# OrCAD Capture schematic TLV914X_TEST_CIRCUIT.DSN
size A; title: TLV914x 18V, Rail-to-Rail I/O, 110kHz Low Power; rev: 1.0; note: Datasheet: SBOSAM4 - DEC 2024 REV. FEB 2026
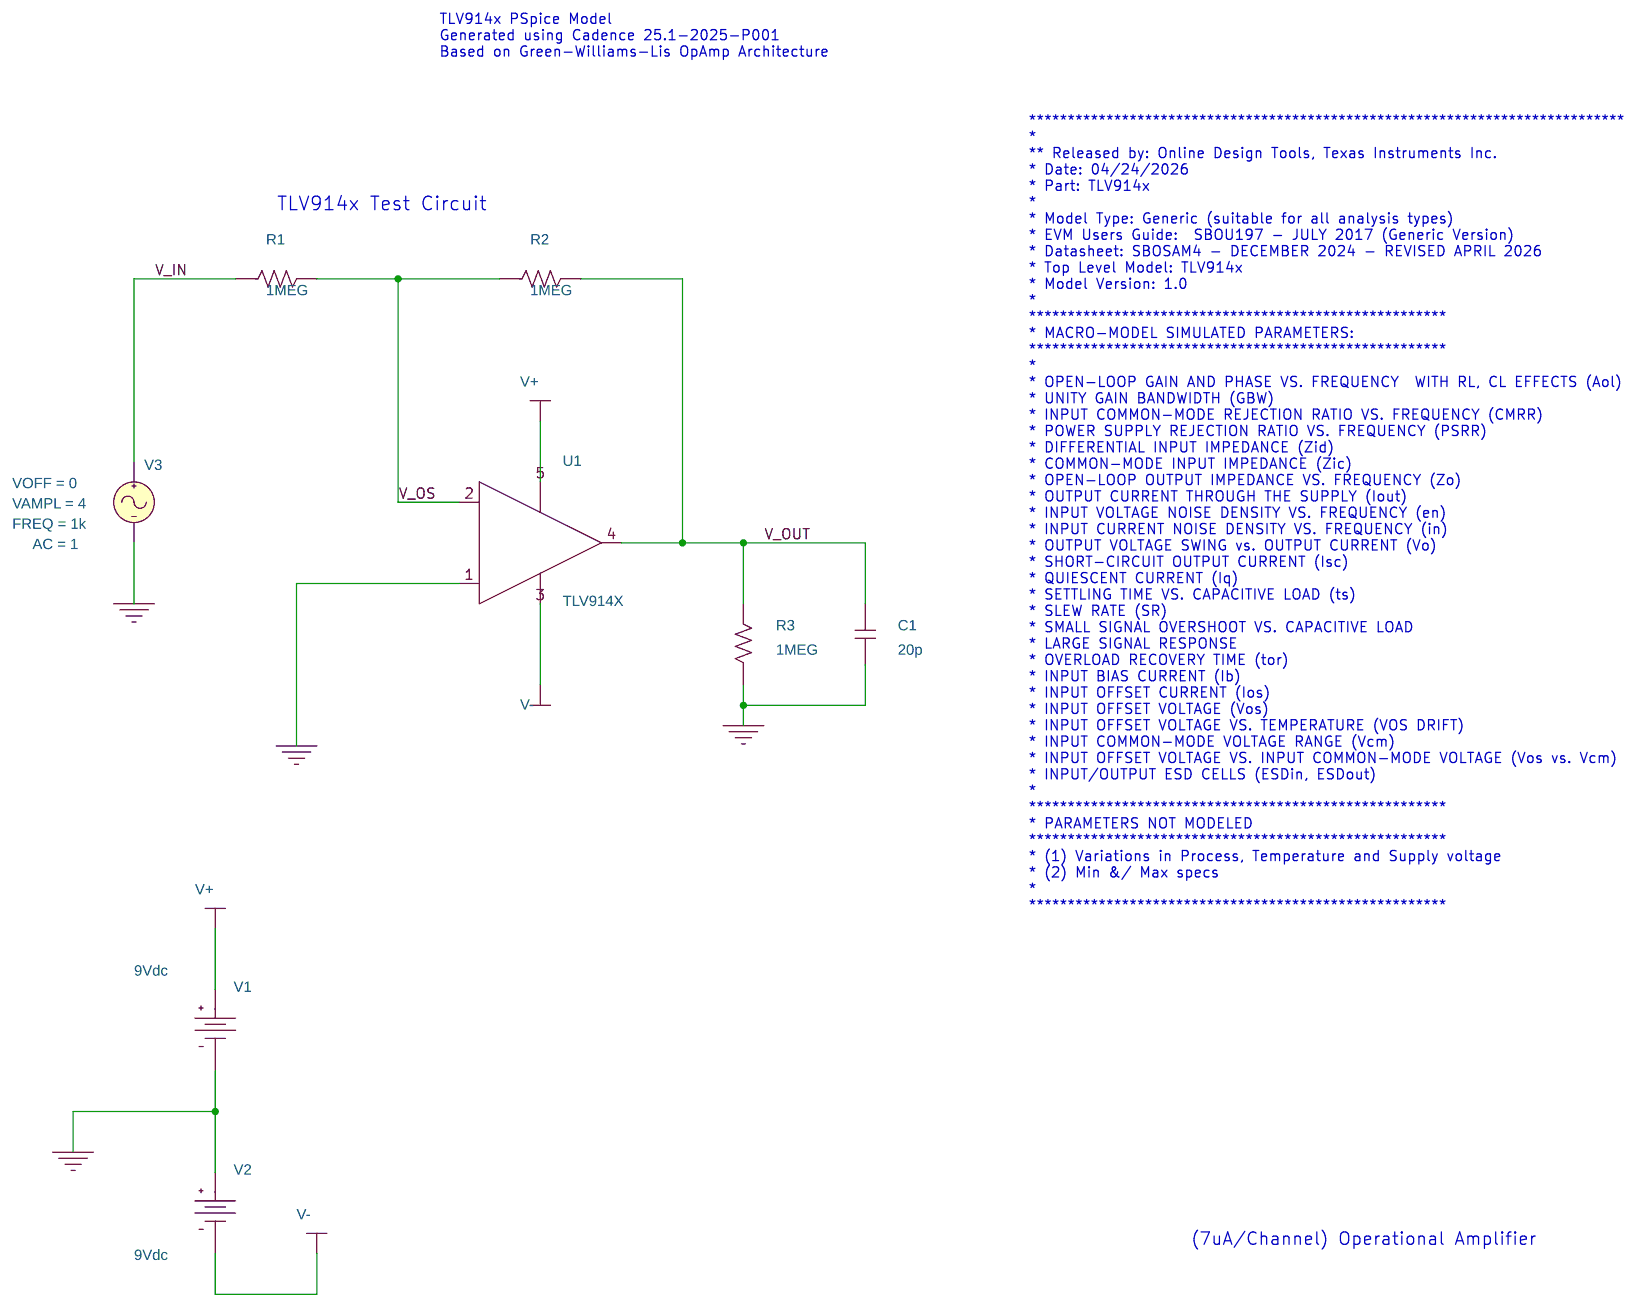
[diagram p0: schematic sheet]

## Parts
C1  20p  [cap196]
R1  1MEG  [AXRC05]
R2  1MEG  [AXRC05]
R3  1MEG  [AXRC05]
U1  TLV914X
V1  VDC
V2  VDC
V3  VSIN

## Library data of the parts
C1 = C
R1-R3 = R
U1 = TLV914X
V1 V2 = VDC: DC: 9Vdc
V3 = VSIN: AC: 1; AppProp: Sine$Voltage$0$-1; DC: 0; FREQ: 1k; TD: 10u; VAMPL: 4; VOFF: 0

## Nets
0: C1.1 R3.1 U1.1(+) V1.1(-) V2.0(+) V3.2(-)
V+: U1.5(V+) V1.0(+)
V-: U1.3(V-) V2.1(-)
V_IN: R1.1 V3.1(+)
V_OS: R1.2 R2.1 U1.2(-)
V_OUT: C1.2 R2.2 R3.2 U1.4(OUT)

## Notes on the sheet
- TLV914x PSpice Model
  Generated using Cadence 25.1-2025-P001
  Based on Green-Williams-Lis OpAmp Architecture
- *****************************************************************************
  *
  ** Released by: Online Design Tools, Texas Instruments Inc.
  * Date: 04/24/2026
  * Part: TLV914x
  *
  * Model Type: Generic (suitable for all analysis types)
  * EVM Users Guide:  SBOU197 - JULY 2017 (Generic Version)
  * Datasheet: SBOSAM4 - DECEMBER 2024 - REVISED APRIL 2026
  * Top Level Model: TLV914x
  * Model Version: 1.0
  *
  ******************************************************
  * MACRO-MODEL SIMULATED PARAMETERS:
  ******************************************************
  *
  * OPEN-LOOP GAIN AND PHASE VS. FREQUENCY  WITH RL, CL EFFECTS (Aol)
  * UNITY GAIN BANDWIDTH (GBW)
  * INPUT COMMON-MODE REJECTION RATIO VS. FREQUENCY (CMRR)
  * POWER SUPPLY REJECTION RATIO VS. FREQUENCY (PSRR)
  * DIFFERENTIAL INPUT IMPEDANCE (Zid)
  * COMMON-MODE INPUT IMPEDANCE (Zic)
  * OPEN-LOOP OUTPUT IMPEDANCE VS. FREQUENCY (Zo)
  * OUTPUT CURRENT THROUGH THE SUPPLY (Iout)
  * INPUT VOLTAGE NOISE DENSITY VS. FREQUENCY (en)
  * INPUT CURRENT NOISE DENSITY VS. FREQUENCY (in)
  * OUTPUT VOLTAGE SWING vs. OUTPUT CURRENT (Vo)
  * SHORT-CIRCUIT OUTPUT CURRENT (Isc)
  * QUIESCENT CURRENT (Iq)
  * SETTLING TIME VS. CAPACITIVE LOAD (ts)
  * SLEW RATE (SR)
  * SMALL SIGNAL OVERSHOOT VS. CAPACITIVE LOAD
  * LARGE SIGNAL RESPONSE
  * OVERLOAD RECOVERY TIME (tor)
  * INPUT BIAS CURRENT (Ib)
  * INPUT OFFSET CURRENT (Ios)
  * INPUT OFFSET VOLTAGE (Vos)
  * INPUT OFFSET VOLTAGE VS. TEMPERATURE (VOS DRIFT)
  * INPUT COMMON-MODE VOLTAGE RANGE (Vcm)
  * INPUT OFFSET VOLTAGE VS. INPUT COMMON-MODE VOLTAGE (Vos vs. Vcm)
  * INPUT/OUTPUT ESD CELLS (ESDin, ESDout)
  *
  ******************************************************
  * PARAMETERS NOT MODELED
  ******************************************************
  * (1) Variations in Process, Temperature and Supply voltage
  * (2) Min &/ Max specs
  *
  ******************************************************
- TLV914x Test Circuit
- (7uA/Channel) Operational Amplifier
